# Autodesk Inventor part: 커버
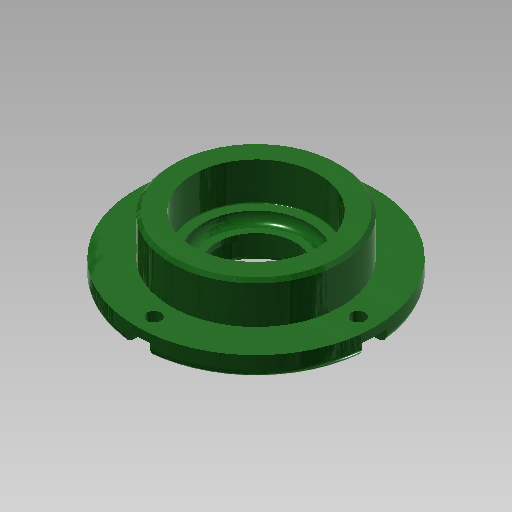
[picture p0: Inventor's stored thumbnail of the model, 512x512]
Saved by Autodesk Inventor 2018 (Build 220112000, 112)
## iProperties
Company: 한국ATC센터
Created: 2016-04
Part Number: 커버
Document SubType Name: Modeling
Designer: mdu
Density: 7.86 g/cm^3
Mass: 351.567 g
Surface Area: 161.165 cm^2
Volume: 44.7286 cm^3
Material: 강철, 연강
Appearance: 진녹색
Author: mdu
Revision Number: 1
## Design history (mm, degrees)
sketch "스케치1"
  geometry: C1 r 38 at (0, 0); 1 further point
  constraints: 1 centre point, 1 coincident
  dimensions: "d0" = 76 diameter of C1
extrude "돌출1" new body sketch "스케치1" distance "d1" = 7; taper "d2" = 0 deg
sketch "스케치2"
  geometry: C1 r 27 at (0, 0); 1 further point
  constraints: 1 centre point, 1 coincident
  dimensions: "d3" = 54 diameter of C1
extrude "돌출2" join sketch "스케치2" distance "d4" = 13; taper "d5" = 0 deg
sketch "스케치3"
  geometry: C1 r 20 at (0, 0); 1 further point
  constraints: 1 centre point, 1 coincident
  dimensions: "d6" = 40 diameter of C1
extrude "돌출3" join sketch "스케치3" distance "d7" = 5; taper "d8" = 0 deg
hole "구멍1" diameter "d11" = 25; stored, may be unused: countersink angle "d15" = 90 deg, drill point angle "d17" = 118 deg; dims "d9" = 10, "d10" = 10, "d12" = 6, "d13" = 32, "d14" = 8.3, "d16" = 8
hole "구멍2" diameter "d20" = 34; stored, may be unused: countersink angle "d24" = 90 deg, drill point angle "d26" = 0 deg; dims "d18" = 10, "d19" = 10, "d21" = 6, "d22" = 40, "d23" = 12, "d25" = 3
fillet "모깎기2" dims "d34" = 3
fillet "모깎기1" dims "d27" = 0.3
chamfer "모따기1" distance "d28" = 1; stored, may be unused: second distance "d29" = 2, angle "d30" = 45 deg
chamfer "모따기2" distance "d31" = 1.2; stored, may be unused: second distance "d32" = 2, angle "d33" = 30 deg
sketch "스케치4" dims "d35" = 65
  geometry: 3 further points
  constraints: 2 horizontal alignment, 1 coincident, 2 other
hole "구멍3" sketch "스케치4" at (32.5, 0) diameter "d36" = 4.5; stored, may be unused: countersink angle "d40" = 90 deg, drill point angle "d42" = 118 deg; dims "d37" = 6, "d38" = 8, "d39" = 4.4, "d41" = 13
sketch "스케치5"
  geometry: L1 (0, 4)-(5.5, 4); L2 (5.5, 4)-(5.5, -4); L3 (5.5, -4)-(0, -4); L4 (0, -4)-(0, 4); C1 r 2.25 at (0, 0) reference; C2 r 38 at (-32.5, 0) reference; 2 further points
  constraints: 8 end point, 3 horizontal, 2 parallel, 1 perpendicular, 1 tangent, 1 vertical alignment, 1 other
extrude "돌출4" cut sketch "스케치5" extent not by distance; stored distance "d47" = 24.5; taper "d48" = 0 deg
node "솔리드1"
pattern_circular "원형 패턴1" dims angle "d44" = 360 deg
pattern_circular "원형 패턴2" dims angle "d50" = 360 deg
node "투영된 루프1"
